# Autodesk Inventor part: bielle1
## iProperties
Shininess: 20.0
Angle Display Precision: 2
Document Length Units: 11269
Document Angle Units: 11279
Document Time Units: 11290
Document Mass Units: 11283
Document Length Units Precision: 3
Document Angle Units Precision: 2
Compacted: True
Created: 2009-07
Part Number: bielle1
Material: Par défaut
Document SubType Name: Modélisation
Designer: EL
Density: 1 g/cm^3
Density: 0.0
Volumn: 0.0
Area: 0.0
PropertySet Name: Model Information
Control State: 0
Master: False
Checked Out: False
Author: EL
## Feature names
1. Extrusion1
2. Extrusion2
